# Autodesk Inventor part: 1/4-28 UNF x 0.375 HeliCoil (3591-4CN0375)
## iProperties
Title: 1/4-28 UNF x 0.375 HeliCoil (3591-4CN0375)
Author: CFitzwater
Shininess: 64.0
Angle Display Precision: 2
Document Length Units: 11272
Document Angle Units: 11286
Document Time Units: 11279
Document Mass Units: 11290
Document Length Units Precision: 3
Document Angle Units Precision: 2
Compacted: True
PropertySet Name: _Private Model Information
Created: 2002-02
Part Number: Helicoil-3591-CN
Material: Stainless Steel, Austenitic
Document SubType Name: Modeling
Designer: CFitzwater
Control State: 0
Master: False
Checked Out: False
PropertySet Name: Design Tracking Control
Density: 7.750000000000001
Volumn: 0.37239295650448834
Area: 5.5389113408432396
PropertySet Name: Model Information
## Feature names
1. Extrusion1
2. Chamfer1
3. Chamfer2
